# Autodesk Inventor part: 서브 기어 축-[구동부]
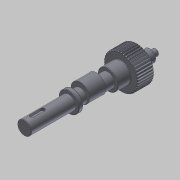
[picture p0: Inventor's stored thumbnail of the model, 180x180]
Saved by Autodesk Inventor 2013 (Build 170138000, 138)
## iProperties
Created: 2018-12
Part Number: 서브 기어 축-[구동부]
Material: 강철, 연강
Document SubType Name: Modeling
Designer: mduedu
Categories: <?xml version="1.0" encoding="UTF-16"?> <MemberInstance><Categories><FamilyTemplate><FamilyTemplateParameter ValueType="xs:double" Id="1" ObjectReferenceKey="da
Density: 1 g/cm^3
Author: mduedu
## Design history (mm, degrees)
sketch "Sketch1"
  geometry: C1 r 21.3 at (0, 0)
  constraints: 1 centre point
  dimensions: "d0" = 42.6 diameter of C1 (= da_da)
extrude "Extrusion1" new body sketch "Sketch1" distance "d1" = 20 (= da_b); taper "d2" = 0 deg
workplane "Work Plane2"
sketch "Sketch2"
  geometry: C1 r 21.3 at (0, 0) reference; C2 r 20.5 at (0, 0)
  constraints: 1 centre point, 1 coincident
  dimensions: "d3" = 41 diameter of C2 (= da_dw)
feature "피치 지름" sketch "Sketch2" dims "d4" = 10, "d5" = 0
workplane "Work Plane8"
workplane "Work Plane9"
chamfer "모따기1" distance "d49" = 1; stored, may be unused: second distance "d50" = 2, angle "d51" = 45 deg
sketch "스케치3"
  geometry: C1 r 12.5 at (0, 0); 1 further point
  constraints: 1 centre point, 1 coincident
  dimensions: "d52" = 25 diameter of C1
extrude "돌출2" join sketch "스케치3" distance "d53" = 16; taper "d54" = 0 deg
sketch "스케치4"
  geometry: C1 r 8.5 at (0, 0); 1 further point
  constraints: 1 centre point, 1 coincident
  dimensions: "d55" = 17 diameter of C1
extrude "돌출3" join sketch "스케치4" distance "d56" = 103; taper "d57" = 0 deg
sketch "스케치5"
  geometry: C1 r 7.5 at (0, 0); 1 further point
  constraints: 1 centre point, 1 coincident
  dimensions: "d58" = 15 diameter of C1
extrude "돌출4" join sketch "스케치5" distance "d59" = 16; taper "d60" = 0 deg
sketch "스케치6"
  geometry: C1 r 4 at (0, 0); 1 further point
  constraints: 1 centre point, 1 coincident
  dimensions: "d61" = 8 diameter of C1
extrude "돌출5" join sketch "스케치6" distance "d62" = 7; taper "d63" = 0 deg
chamfer "모따기2" distance "d64" = 0.5; stored, may be unused: second distance "d65" = 2, angle "d66" = 45 deg
fillet "모깎기1" dims "d67" = 0.5
feature "스퍼 기어" dims "da_b" = 20, "da_d" = 41, "da_aw" = 31, "da_da" = 42.6, "da_df" = 39.086, "da_dw" = 41, angle "da_beta" = 0 deg, "da_lefttooth" = 0, "da_righttooth" = 0
node "작업 평면11"
sketch "스케치7"
  geometry: C1 r 11.5 at (0, 3); C2 r 8.5 at (0, 0) reference; 1 further point
  constraints: 1 centre point, 1 tangent, 1 vertical alignment
  dimensions: "d69" = 3 distance of point (0, 0) C1.centre; "d70" = 23 diameter of C1 (derived)
extrude "돌출6" join sketch "스케치7" stored distance "d71" = 20; taper "d72" = 0 deg
node "작업 평면12"
sketch "스케치8"
  geometry: C1 r 12.5 at (0, 0) reference; C2 r 12.5 at (0, 0) reference; 1 further point
extrude "돌출7" join sketch "스케치8" distance "d74" = 5; taper "d75" = 0 deg
chamfer "모따기3" distance "d76" = 0.5; stored, may be unused: second distance "d77" = 2, angle "d78" = 45 deg
sketch "스케치9"
  geometry: L1 (-8, 139)-(8, 139) reference; L2 (0, 139)-(0, 0); L3 (-8.5, 84)-(-8.5, 138.5) reference; L4 (-8.5, 115)-(0, 115); L5 (-8.5, 115)-(-8.5, 113.5); L6 (-8.5, 113.5)-(-7, 115); L7 (-7, 115)-(-8.5, 115)
  constraints: 10 end point, 4 point on line, 2 perpendicular, 1 collinear, 1 midpoint
  dimensions: "d79" = 24 distance between parallel lines of L4 L1; "d80" = 3 diameter of L5.end L4; "d81" = 45 deg angle of L6 L3
revolve "회전1" sketch "스케치9" stored, may be unused: angle "d82" = 90 deg
sketch "스케치10"
  geometry: L1 (-8.5, 116.5)-(-7, 115) reference; L2 (-8.5, 113.5)-(-7, 115) reference; 2 further points
  constraints: 1 coincident
node "작업점1"
node "작업 평면13"
sketch "스케치11"
  geometry: L1 (-2.5, 93.5)-(-2.5, 80.5); L2 (2.5, 80.5)-(2.5, 93.5); L3 (-8, 103)-(8, 103) reference; A1 r 2.5 centre (0, 93.5) between (2.5, 93.5) and (-2.5, 93.5); A2 r 2.5 centre (0, 80.5) between (-2.5, 80.5) and (2.5, 80.5); 1 further point
  constraints: 4 end point, 4 point on circle, 4 tangent, 2 centre point, 2 vertical alignment, 1 parallel
  dimensions: "d83" = 7 distance edge to line of A1 L3; "d84" = 18 dimension on A2 A1; "d85" = 5 distance between parallel lines of L1 L2
extrude "돌출8" cut sketch "스케치11" distance "d86" = 3; taper "d87" = 0 deg
sketch "스케치12" dims "d88" = 32
  geometry: C1 r 0.5 at (0, -16); 2 further points
  constraints: 2 vertical alignment, 1 centre point, 1 coincident, 2 other
  dimensions: "d89" = 1 diameter of C1
extrude "돌출9" join sketch "스케치12" distance "d90" = 0.3; taper "d91" = 0 deg
sketch "스케치13"
  geometry: C1 r 11.5 at (0, 3) reference; 1 further point
  node "절단 모서리 투영1"
body "Solid1"
body "Srf1"
node "투영된 루프1"
other parameters: "d16" = 31 (= da_aw), "d17" = 0, "d34" = 0.76624 (computed from da_z), "d39" = 0, "d41" = 0, "d43" = 31 (= da_aw), "d46" = 31 (= da_aw), "d47" = 0, "d48" = 0, "d68" = 24, "d73" = 48
